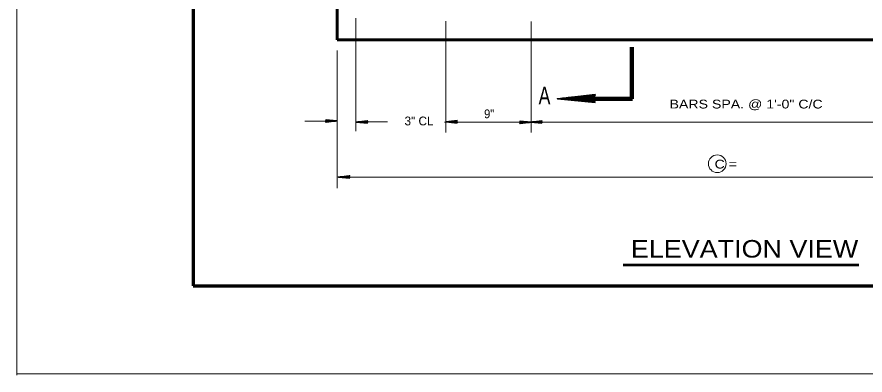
# Model space of a CAD drawing. Extents: x 4.49 to 7.69, y 0.28 to 2.27.
# Drawn here: x 4.492 to 5.296, y 0.282 to 0.621 of the extents above; entities that cross this region are included whole.
import ezdxf

# ---------------------------------------------------------------- set-up
doc = ezdxf.new("R2010")
doc.units = 0
doc.header["$LTSCALE"] = 0.0033
doc.layers.add('1', color=7, linetype='Continuous', lineweight=35)

msp = doc.modelspace()

# ---------------------------------------------------------------- linework, layer by layer
at = {"layer": '1', "lineweight": 13}
for p, q in [((4.492417, 0.281583), (4.492417, 2.269833)), ((4.813417, 0.619583), (4.813417, 0.512583)), ((4.898583, 0.616583), (4.898583, 0.511167)), ((4.97925, 0.61625), (4.97925, 0.511167)), ((4.79575, 0.588833), (4.79575, 0.458667)), ((4.764917, 0.522083), (4.78575, 0.522083)), ((4.822417, 0.521333), (4.84325, 0.521333)), ((5.448417, 0.521167), (4.897333, 0.521167)), ((4.796917, 0.469), (5.179917, 0.469)), ((5.179917, 0.469), (5.545333, 0.469)), ((7.689167, 0.28275), (4.492417, 0.28275))]:
    msp.add_line(p, q, dxfattribs=at)
at = {"layer": '1', "lineweight": 60}
for p, q in [((5.14175, 0.599083), (4.79575, 0.599083)), ((5.54575, 0.599083), (5.122333, 0.599083))]:
    msp.add_line(p, q, dxfattribs=at)
at = {"layer": '1', "lineweight": 90}
for p, q in [((5.074667, 0.592), (5.074667, 0.574167)), ((5.074667, 0.584667), (5.074667, 0.543)), ((5.075333, 0.543167), (5.033667, 0.543167))]:
    msp.add_line(p, q, dxfattribs=at)
at = {"layer": '1'}
for p, q in [((5.039167, 0.547), (5.014417, 0.54425)), ((5.039167, 0.5465), (5.014417, 0.543833)), ((5.039917, 0.54325), (5.00425, 0.54325)), ((5.039167, 0.5405), (5.012583, 0.543833)), ((5.039167, 0.5405), (5.012583, 0.54325)), ((5.039167, 0.539833), (5.012583, 0.543083)), ((5.039167, 0.539833), (5.012583, 0.543083)), ((5.039167, 0.54025), (5.012583, 0.543083)), ((5.039167, 0.546083), (5.014417, 0.54325)), ((5.039417, 0.5455), (5.0145, 0.543083)), ((4.784833, 0.52225), (4.795417, 0.52225)), ((4.785, 0.521583), (4.792333, 0.522333)), ((4.785083, 0.52325), (4.792917, 0.522333)), ((4.785083, 0.52325), (4.792917, 0.522333)), ((4.785083, 0.523167), (4.792917, 0.522333)), ((4.785083, 0.523083), (4.792917, 0.52225)), ((4.785083, 0.523083), (4.792917, 0.522083)), ((4.785083, 0.521417), (4.792417, 0.52225)), ((4.785083, 0.521333), (4.792417, 0.522083)), ((4.824, 0.52225), (4.816667, 0.521417)), ((4.824, 0.522083), (4.816667, 0.521333)), ((4.908917, 0.522417), (4.901583, 0.521583)), ((4.908917, 0.52225), (4.901583, 0.5215)), ((4.908917, 0.522167), (4.901583, 0.521333)), ((4.989333, 0.522167), (4.982, 0.521333)), ((4.785083, 0.521167), (4.792417, 0.522)), ((4.82425, 0.521167), (4.813667, 0.521167)), ((4.824, 0.520333), (4.816167, 0.521333)), ((4.824, 0.520333), (4.816167, 0.521167)), ((4.824, 0.520167), (4.816167, 0.521083)), ((4.824, 0.520167), (4.816167, 0.521083)), ((4.824, 0.52025), (4.816167, 0.521083)), ((4.824, 0.522), (4.816667, 0.521167)), ((4.824083, 0.521833), (4.81675, 0.521083)), ((4.909167, 0.521333), (4.898583, 0.521333)), ((4.908917, 0.5205), (4.901083, 0.5215)), ((4.908917, 0.5205), (4.901083, 0.521333)), ((4.908917, 0.520333), (4.901083, 0.52125)), ((4.908917, 0.520333), (4.901083, 0.52125)), ((4.908917, 0.520417), (4.901083, 0.52125)), ((4.909, 0.522), (4.901667, 0.52125)), ((4.968667, 0.520917), (4.97925, 0.520917)), ((4.968833, 0.52025), (4.976167, 0.521)), ((4.968917, 0.521917), (4.97675, 0.521)), ((4.968917, 0.521917), (4.97675, 0.521)), ((4.968917, 0.521833), (4.97675, 0.521)), ((4.968917, 0.52175), (4.97675, 0.520917)), ((4.968917, 0.52175), (4.97675, 0.52075)), ((4.968917, 0.520083), (4.97625, 0.520917)), ((4.968917, 0.52), (4.97625, 0.52075)), ((4.968917, 0.519833), (4.97625, 0.520667)), ((4.989583, 0.521083), (4.979, 0.521083)), ((4.989333, 0.52025), (4.9815, 0.52125)), ((4.989333, 0.52025), (4.9815, 0.521083)), ((4.989333, 0.520083), (4.9815, 0.521)), ((4.989333, 0.520083), (4.9815, 0.521)), ((4.989333, 0.520167), (4.9815, 0.521)), ((4.989333, 0.522), (4.982, 0.52125)), ((4.989333, 0.521917), (4.982, 0.521083)), ((4.989417, 0.52175), (4.982083, 0.521)), ((4.807417, 0.469083), (4.796833, 0.469083)), ((4.807167, 0.46825), (4.799333, 0.46925)), ((4.807167, 0.46825), (4.799333, 0.469083)), ((4.807167, 0.468083), (4.799333, 0.469)), ((4.807167, 0.468083), (4.799333, 0.469)), ((4.807167, 0.468167), (4.799333, 0.469)), ((4.807167, 0.470167), (4.799833, 0.469333)), ((4.807167, 0.47), (4.799833, 0.46925)), ((4.807167, 0.469917), (4.799833, 0.469083)), ((4.80725, 0.46975), (4.799917, 0.469))]:
    msp.add_line(p, q, dxfattribs=at)
at = {"layer": '1', "lineweight": 53}
msp.add_line((5.066333, 0.386083), (5.289583, 0.386083), dxfattribs=at)
at = {"layer": '1', "lineweight": 70}
msp.add_line((4.659167, 0.366083), (7.605833, 0.366083), dxfattribs=at)
msp.add_lwpolyline([(7.605833, 0.366083), (7.605833, 2.186167), (4.659167, 2.186167), (4.659167, 0.366083)], dxfattribs=at)
at = {"layer": '1', "lineweight": 60}
msp.add_lwpolyline([(4.79575, 0.599083), (4.79575, 0.682417), (4.879083, 0.682417), (4.879083, 1.01575)], dxfattribs=at)
at = {"layer": '1', "lineweight": 40}
msp.add_lwpolyline([(4.659167, 0.366083), (7.020833, 0.366083), (7.020833, 0.691167), (7.605833, 0.691167)], dxfattribs=at)
at = {"layer": '1'}
for points in [[(5.039917, 0.53975), (5.00425, 0.54325), (5.039917, 0.54725), (5.038, 0.54325)], [(5.0375, 0.543083), (5.021667, 0.54275), (5.021667, 0.543083), (5.024667, 0.543083), (5.0375, 0.54275), (5.02725, 0.5425), (5.038, 0.542083), (5.03025, 0.542), (5.038, 0.541583), (5.026167, 0.5425), (5.010333, 0.543083), (5.013417, 0.543833), (5.00925, 0.543833), (5.0375, 0.543833), (5.029167, 0.544333), (5.038, 0.544333), (5.02, 0.543083), (5.038, 0.545333)], [(4.784833, 0.523333), (4.795417, 0.52225), (4.784833, 0.521083), (4.785417, 0.52225)], [(4.785583, 0.522333), (4.79025, 0.522417), (4.79025, 0.522333), (4.789333, 0.522333), (4.785583, 0.522417), (4.788583, 0.5225), (4.785417, 0.522583), (4.787667, 0.522667), (4.785417, 0.52275), (4.788917, 0.5225), (4.793583, 0.522333), (4.792667, 0.522083), (4.793917, 0.522083), (4.785583, 0.522083), (4.788, 0.521917), (4.785417, 0.521917), (4.79075, 0.522333), (4.785417, 0.521667)], [(4.82425, 0.520083), (4.813667, 0.521167), (4.82425, 0.522333), (4.823667, 0.521167)], [(4.909167, 0.52025), (4.898583, 0.521333), (4.909167, 0.5225), (4.908583, 0.521333)], [(4.989583, 0.52), (4.979, 0.521083), (4.989583, 0.52225), (4.989, 0.521083)], [(4.8235, 0.521083), (4.818833, 0.521), (4.818833, 0.521083), (4.81975, 0.521083), (4.8235, 0.521), (4.8205, 0.520917), (4.823667, 0.520833), (4.821417, 0.52075), (4.823667, 0.520667), (4.820167, 0.520917), (4.8155, 0.521083), (4.816417, 0.521333), (4.815167, 0.521333), (4.8235, 0.521333), (4.821083, 0.5215), (4.823667, 0.5215), (4.818333, 0.521083), (4.823667, 0.52175)], [(4.908417, 0.52125), (4.90375, 0.521167), (4.90375, 0.52125), (4.904667, 0.52125), (4.908417, 0.521167), (4.905417, 0.521083), (4.908583, 0.521), (4.906333, 0.520917), (4.908583, 0.520833), (4.905083, 0.521083), (4.900417, 0.52125), (4.901333, 0.5215), (4.900083, 0.5215), (4.908417, 0.5215), (4.906, 0.521667), (4.908583, 0.521667), (4.90325, 0.52125), (4.908583, 0.521917)], [(4.968667, 0.522), (4.97925, 0.520917), (4.968667, 0.51975), (4.96925, 0.520917)], [(4.969417, 0.521), (4.974083, 0.521083), (4.974083, 0.521), (4.973167, 0.521), (4.969417, 0.521083), (4.972417, 0.521167), (4.96925, 0.52125), (4.9715, 0.521333), (4.96925, 0.521417), (4.97275, 0.521167), (4.977417, 0.521), (4.9765, 0.52075), (4.97775, 0.52075), (4.969417, 0.52075), (4.971833, 0.520583), (4.96925, 0.520583), (4.974583, 0.521), (4.96925, 0.520333)], [(4.988833, 0.521), (4.984167, 0.520917), (4.984167, 0.521), (4.985083, 0.521), (4.988833, 0.520917), (4.985833, 0.520833), (4.989, 0.52075), (4.98675, 0.520667), (4.989, 0.520583), (4.9855, 0.520833), (4.980833, 0.521), (4.98175, 0.52125), (4.9805, 0.52125), (4.988833, 0.52125), (4.986417, 0.521417), (4.989, 0.521417), (4.983667, 0.521), (4.989, 0.521667)], [(4.807417, 0.468), (4.796833, 0.469083), (4.807417, 0.47025), (4.806833, 0.469083)], [(4.806667, 0.469), (4.802, 0.468917), (4.802, 0.469), (4.802917, 0.469), (4.806667, 0.468917), (4.803667, 0.468833), (4.806833, 0.46875), (4.804583, 0.468667), (4.806833, 0.468583), (4.803333, 0.468833), (4.798667, 0.469), (4.799583, 0.46925), (4.798333, 0.46925), (4.806667, 0.46925), (4.80425, 0.469417), (4.806833, 0.469417), (4.8015, 0.469), (4.806833, 0.469667)]]:
    msp.add_lwpolyline(points, close=True, dxfattribs=at)
for points in [[(5.0375, 0.543083), (5.03875, 0.5405), (5.038, 0.541333), (5.0375, 0.5425), (5.0365, 0.542083), (5.037167, 0.541), (5.037667, 0.543583), (5.03825, 0.545333), (5.039167, 0.546583)], [(4.785583, 0.522333), (4.785167, 0.523083), (4.785417, 0.522833), (4.785583, 0.5225), (4.785833, 0.522583), (4.785667, 0.522917), (4.7855, 0.522167), (4.785333, 0.521667), (4.785083, 0.52125)], [(4.8235, 0.521083), (4.823917, 0.520333), (4.823667, 0.520583), (4.8235, 0.520917), (4.82325, 0.520833), (4.823417, 0.5205), (4.823583, 0.52125), (4.82375, 0.52175), (4.824, 0.522167)], [(4.908417, 0.52125), (4.908833, 0.5205), (4.908583, 0.52075), (4.908417, 0.521083), (4.908167, 0.521), (4.908333, 0.520667), (4.9085, 0.521417), (4.908667, 0.521917), (4.908917, 0.522333)], [(4.988833, 0.521), (4.98925, 0.52025), (4.989, 0.5205), (4.988833, 0.520833), (4.988583, 0.52075), (4.98875, 0.520417), (4.988917, 0.521167), (4.989083, 0.521667), (4.989333, 0.522083)], [(4.969417, 0.521), (4.969, 0.52175), (4.96925, 0.5215), (4.969417, 0.521167), (4.969667, 0.52125), (4.9695, 0.521583), (4.969333, 0.520833), (4.969167, 0.520333), (4.968917, 0.519917)], [(4.806667, 0.469), (4.807083, 0.46825), (4.806833, 0.4685), (4.806667, 0.468833), (4.806417, 0.46875), (4.806583, 0.468417), (4.80675, 0.469167), (4.806917, 0.469667), (4.807167, 0.470083)]]:
    msp.add_lwpolyline(points, dxfattribs=at)
at = {"layer": '1', "lineweight": 13}
msp.add_circle((5.155583, 0.481667), 0.008333, dxfattribs=at)

# ---------------------------------------------------------------- texts
at = {"layer": '1'}
for s, height, width, p in [('A', 0.01667, 0.75, (4.986417, 0.537917)), ('BARS SPA. @ 1\'-0" C/C', 0.008334, 1.2, (5.110417, 0.534)), ('9"', 0.008334, 0.95, (4.93475, 0.52475)), ('C =      ', 0.008334, 1.2, (5.153083, 0.477167)), ('ELEVATION VIEW', 0.01658, 1.15, (5.07375, 0.392833))]:
    msp.add_text(s, height=height, dxfattribs=dict(at, width=width)).set_placement(p)
msp.add_text('3" CL', height=0.008334, dxfattribs=at).set_placement((4.859417, 0.518))

doc.saveas('drawing.dxf')
